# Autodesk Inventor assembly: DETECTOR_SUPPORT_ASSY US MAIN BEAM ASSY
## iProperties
Shininess: 64.0
Length Units: 11272
Angle Units: 11279
Time Units: 11290
Mass Units: 11286
Length Display Precision: 3
Angle Display Precision: 2
Compacted: True
Part Number: DETECTOR_SUPPORT_ASSY US MAIN BEAM ASSY
Document SubType Name: Assembly
Created: 2004-08
Designer: John Blackburn
Manufacturer: Standard
Standards Organization: Custom
Density: 0.0
Volumn: 0.0
Area: 0.0
PropertySet Name: Model Information
Control State: 0
Master: False
Checked Out: False
Author: John Blackburn
